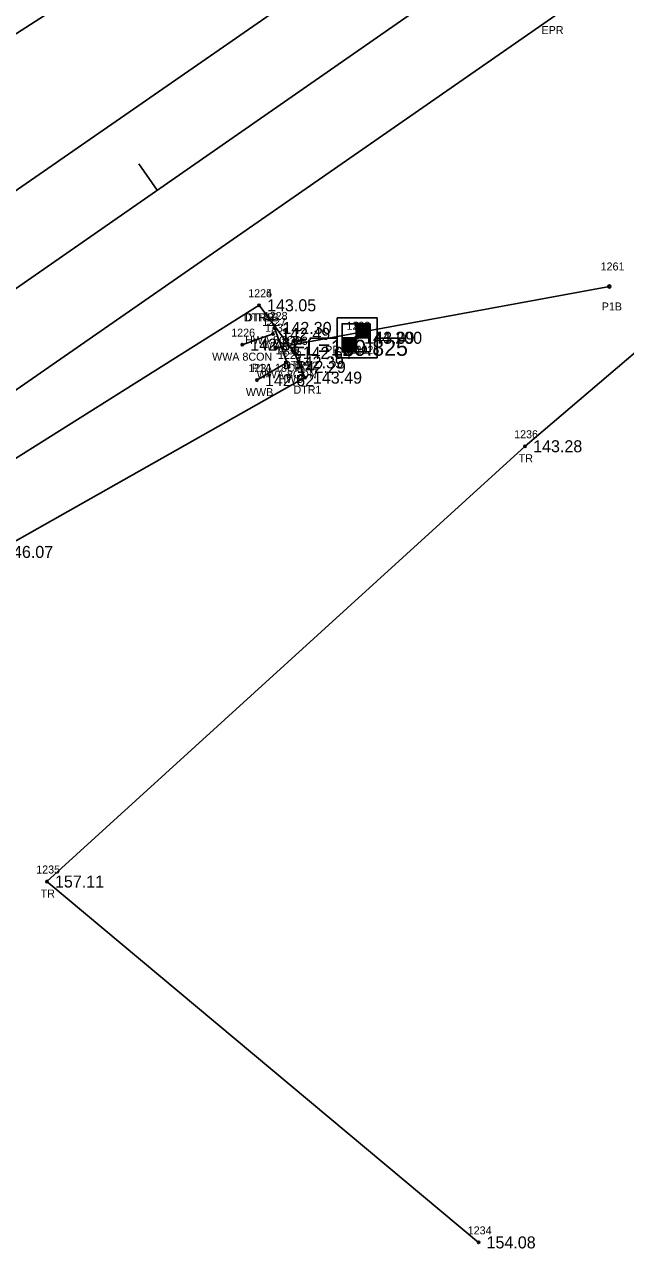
# Model space of a CAD drawing. Extents: x 2449052 to 2452984, y 1012343 to 1015262.
# Drawn here: x 2450757.2 to 2450832.3, y 1013613.6 to 1013766.6 of the extents above; entities that cross this region are included whole.
import ezdxf

# ---------------------------------------------------------------- set-up
doc = ezdxf.new("R2010")
doc.units = 0
for name, color, linetype in [('RD_EX_Bridge', 7, 'Continuous'), ('RD_EX_Bridge_txCode', 7, 'Continuous'), ('RD_EX_DR_Pipe', 7, 'Continuous'), ('RD_EX_DR_Pipe_txCode', 7, 'Continuous'), ('RD_EX_H2O', 7, 'Continuous'), ('RD_EX_H2O_txCode', 7, 'Continuous'), ('RD_EX_Road', 7, 'Continuous'), ('RD_EX_Road_txCode', 7, 'Continuous'), ('RD_EX_TX_Bridge_ELEV', 7, 'Continuous'), ('RD_EX_TX_H2O_ELEV', 7, 'Continuous'), ('RD_EX_TX_VEG_ELEV', 7, 'Continuous'), ('RD_EX_UT', 7, 'Continuous'), ('RD_EX_UT_txCode', 7, 'Continuous'), ('RD_EX_VEG', 7, 'Continuous'), ('RD_EX_VEG_txCode', 7, 'Continuous'), ('RD_HC_Cl', 7, 'Continuous'), ('RD_HC_Data_Tic', 7, 'Continuous'), ('RD_HC_Survey', 7, 'Continuous'), ('RD_HC_Survey_ELEV', 7, 'Continuous'), ('RD_HC_Survey_txCode', 7, 'Continuous'), ('RD_SMD_Locator', 7, 'Continuous'), ('RD_TX_Pipe_ElevEX', 7, 'Continuous')]:
    doc.layers.add(name, color=color, linetype=linetype)

msp = doc.modelspace()

# ---------------------------------------------------------------- linework, layer by layer
at = {"layer": 'RD_EX_Bridge'}
for p, q in [((2450784.38, 1013726.59), (2450788.24, 1013727.94)), ((2450788.41, 1013728.68), (2450790.18, 1013723.81)), ((2450789.94, 1013724.38), (2450786.22, 1013722.16))]:
    msp.add_line(p, q, dxfattribs=at)
at = {"layer": 'RD_EX_DR_Pipe'}
msp.add_line((2450788.58, 1013726.2), (2450830.24, 1013733.86), dxfattribs=at)
at = {"layer": 'RD_EX_H2O'}
for points in [[(2450167.46, 1013291.72), (2450167.1, 1013295.75), (2450175.19, 1013302.21), (2450253.51, 1013357.72), (2450334.87, 1013415.7), (2450415.19, 1013473.64), (2450493.27, 1013528.65), (2450573.99, 1013585.66), (2450651, 1013636.62), (2450748.48, 1013707.64), (2450786.48, 1013731.51)], [(2450167.46, 1013291.72), (2450171.71, 1013290.19), (2450180.8, 1013296.66), (2450259.89, 1013349.14), (2450344.33, 1013402.02), (2450412.23, 1013445.13), (2450424.15, 1013461.12), (2450474.5, 1013497.19), (2450500.92, 1013517.59), (2450581.65, 1013574.66), (2450655.67, 1013631.45), (2450753.63, 1013700.7), (2450792.21, 1013722.47), (2450790.93, 1013725.57), (2450786.48, 1013731.51)]]:
    msp.add_lwpolyline(points, dxfattribs=at)
at = {"layer": 'RD_EX_Road'}
for points in [[(2449674.89, 1012994.69), (2449752.35, 1013048.28), (2449834.92, 1013105.96), (2449914.72, 1013161.11), (2449995.66, 1013217.59), (2450075.29, 1013272.9), (2450081.34, 1013277.24), (2450093.41, 1013285.64), (2450155.49, 1013328.69), (2450236.05, 1013384.7), (2450317.88, 1013441.24), (2450398.87, 1013497.28), (2450477.09, 1013551.76), (2450555.6, 1013606.73), (2450600.18, 1013637.7), (2450618.08, 1013649.65), (2450627.95, 1013656.57), (2450636.43, 1013662.28), (2450733.79, 1013730.39), (2450811.43, 1013784.18), (2450891.39, 1013839.9), (2450907.04, 1013850.14)], [(2449685.94, 1012977.62), (2449764.81, 1013032.3), (2449846, 1013088.39), (2449925.85, 1013144.07), (2450006.8, 1013200.56), (2450086.45, 1013256.14), (2450125.67, 1013283.43), (2450163.55, 1013309.93), (2450166.36, 1013312.09), (2450247.44, 1013367.98), (2450329.19, 1013424.41), (2450410.32, 1013481.09), (2450488.38, 1013535.38), (2450567.5, 1013590.14), (2450648.09, 1013646.13), (2450745.08, 1013713.3), (2450823, 1013767.39), (2450902.19, 1013823.2), (2450918.14, 1013833.95)]]:
    msp.add_lwpolyline(points, dxfattribs=at)
at = {"layer": 'RD_EX_UT'}
for p, q in [((2450801.24, 1013729.96), (2450796.24, 1013729.96)), ((2450796.24, 1013729.96), (2450796.24, 1013724.96)), ((2450801.24, 1013724.96), (2450801.24, 1013729.96)), ((2450792.81, 1013727.4), (2450796.28, 1013727.4)), ((2450801.17, 1013727.4), (2450804.81, 1013727.4)), ((2450796.24, 1013724.96), (2450801.24, 1013724.96))]:
    msp.add_line(p, q, dxfattribs=at)
at = {"layer": 'RD_EX_VEG'}
for points in [[(2450511.25, 1013744.81), (2450612.22, 1013672.34), (2450883.9, 1013848.07), (2451091.43, 1014003.45), (2451271.45, 1014121.26), (2451583.45, 1014347.48), (2451819.08, 1014511.44), (2452219.54, 1014796.6), (2452332.78, 1014867.52)], [(2450813.9, 1013614.45), (2450759.99, 1013659.53), (2450819.72, 1013713.9), (2450939.16, 1013815.82), (2451225.29, 1014005.48), (2451628.56, 1014273.87), (2452372.22, 1014794.45)]]:
    msp.add_lwpolyline(points, dxfattribs=at)
at = {"layer": 'RD_HC_Cl'}
msp.add_line((2449680.91, 1012986.23), (2452350.19, 1014841.68), dxfattribs=at)
at = {"layer": 'RD_HC_Data_Tic'}
msp.add_line((2450773.75, 1013745.87), (2450771.47, 1013749.16), dxfattribs=at)
at = {"layer": 'RD_HC_Survey'}
for p, q in [((2450798.6, 1013729.2), (2450798.6, 1013725.7)), ((2450798.62, 1013729.2), (2450798.62, 1013727.45)), ((2450798.64, 1013729.2), (2450798.64, 1013727.45)), ((2450798.66, 1013729.2), (2450798.66, 1013727.45)), ((2450798.69, 1013729.2), (2450798.69, 1013727.45)), ((2450798.71, 1013729.2), (2450798.71, 1013727.45)), ((2450798.74, 1013729.2), (2450798.74, 1013727.45)), ((2450798.76, 1013729.2), (2450798.76, 1013727.45)), ((2450798.79, 1013729.2), (2450798.79, 1013727.45)), ((2450798.81, 1013729.2), (2450798.81, 1013727.45)), ((2450798.84, 1013729.2), (2450798.84, 1013727.45)), ((2450798.86, 1013729.2), (2450798.86, 1013727.45)), ((2450798.89, 1013729.2), (2450798.89, 1013727.45)), ((2450798.91, 1013729.2), (2450798.91, 1013727.45)), ((2450798.94, 1013729.2), (2450798.94, 1013727.45)), ((2450798.96, 1013729.2), (2450798.96, 1013727.45)), ((2450798.99, 1013729.2), (2450798.99, 1013727.45)), ((2450799.01, 1013729.2), (2450799.01, 1013727.45)), ((2450799.04, 1013729.2), (2450799.04, 1013727.45)), ((2450799.06, 1013729.2), (2450799.06, 1013727.45)), ((2450799.09, 1013729.2), (2450799.09, 1013727.45)), ((2450799.11, 1013729.2), (2450799.11, 1013727.45)), ((2450799.14, 1013729.2), (2450799.14, 1013727.45)), ((2450799.16, 1013729.2), (2450799.16, 1013727.45)), ((2450799.18, 1013729.2), (2450799.18, 1013727.45)), ((2450799.21, 1013729.2), (2450799.21, 1013727.45)), ((2450799.23, 1013729.2), (2450799.23, 1013727.45)), ((2450799.26, 1013729.2), (2450799.26, 1013727.45)), ((2450799.28, 1013729.2), (2450799.28, 1013727.45)), ((2450799.31, 1013729.2), (2450799.31, 1013727.45)), ((2450799.33, 1013729.2), (2450799.33, 1013727.45)), ((2450799.36, 1013729.2), (2450799.36, 1013727.45)), ((2450799.38, 1013729.2), (2450799.38, 1013727.45)), ((2450799.41, 1013729.2), (2450799.41, 1013727.45)), ((2450799.43, 1013729.2), (2450799.43, 1013727.45)), ((2450799.46, 1013729.2), (2450799.46, 1013727.45)), ((2450799.48, 1013729.2), (2450799.48, 1013727.45)), ((2450799.51, 1013729.2), (2450799.51, 1013727.45)), ((2450799.53, 1013729.2), (2450799.53, 1013727.45)), ((2450799.56, 1013729.2), (2450799.56, 1013727.45)), ((2450799.58, 1013729.2), (2450799.58, 1013727.45)), ((2450799.61, 1013729.2), (2450799.61, 1013727.45)), ((2450799.63, 1013729.2), (2450799.63, 1013727.45)), ((2450799.65, 1013729.2), (2450799.65, 1013727.45)), ((2450799.68, 1013729.2), (2450799.68, 1013727.45)), ((2450799.7, 1013729.2), (2450799.7, 1013727.45)), ((2450799.73, 1013729.2), (2450799.73, 1013727.45)), ((2450799.75, 1013729.2), (2450799.75, 1013727.45)), ((2450799.78, 1013729.2), (2450799.78, 1013727.45)), ((2450799.8, 1013729.2), (2450799.8, 1013727.45)), ((2450799.83, 1013729.2), (2450799.83, 1013727.45)), ((2450799.85, 1013729.2), (2450799.85, 1013727.45)), ((2450799.88, 1013729.2), (2450799.88, 1013727.45)), ((2450799.9, 1013729.2), (2450799.9, 1013727.45)), ((2450799.93, 1013729.2), (2450799.93, 1013727.45)), ((2450799.95, 1013729.2), (2450799.95, 1013727.45)), ((2450799.98, 1013729.2), (2450799.98, 1013727.45)), ((2450800, 1013729.2), (2450800, 1013727.45)), ((2450800.03, 1013729.2), (2450800.03, 1013727.45)), ((2450800.05, 1013729.2), (2450800.05, 1013727.45)), ((2450800.08, 1013729.2), (2450800.08, 1013727.45)), ((2450800.1, 1013729.2), (2450800.1, 1013727.45)), ((2450800.13, 1013729.2), (2450800.13, 1013727.45)), ((2450800.15, 1013729.2), (2450800.15, 1013727.45)), ((2450800.17, 1013729.2), (2450800.17, 1013727.45)), ((2450800.2, 1013729.2), (2450800.2, 1013727.45)), ((2450800.22, 1013729.2), (2450800.22, 1013727.45)), ((2450800.25, 1013729.2), (2450800.25, 1013727.45)), ((2450800.27, 1013729.2), (2450800.27, 1013727.45)), ((2450800.3, 1013729.2), (2450800.3, 1013727.45)), ((2450800.32, 1013729.2), (2450800.32, 1013727.45)), ((2450800.35, 1013727.45), (2450796.85, 1013727.45)), ((2450796.85, 1013727.45), (2450796.85, 1013725.7)), ((2450796.87, 1013727.45), (2450796.87, 1013725.7)), ((2450796.9, 1013727.45), (2450796.9, 1013725.7)), ((2450796.92, 1013727.45), (2450796.92, 1013725.7)), ((2450796.95, 1013727.45), (2450796.95, 1013725.7)), ((2450796.97, 1013727.45), (2450796.97, 1013725.7)), ((2450797, 1013727.45), (2450797, 1013725.7)), ((2450797.02, 1013727.45), (2450797.02, 1013725.7)), ((2450797.05, 1013727.45), (2450797.05, 1013725.7)), ((2450797.07, 1013727.45), (2450797.07, 1013725.7)), ((2450797.1, 1013727.45), (2450797.1, 1013725.7)), ((2450797.12, 1013727.45), (2450797.12, 1013725.7)), ((2450797.14, 1013727.45), (2450797.14, 1013725.7)), ((2450797.17, 1013727.45), (2450797.17, 1013725.7)), ((2450797.19, 1013727.45), (2450797.19, 1013725.7)), ((2450797.22, 1013727.45), (2450797.22, 1013725.7)), ((2450797.24, 1013727.45), (2450797.24, 1013725.7)), ((2450797.27, 1013727.45), (2450797.27, 1013725.7)), ((2450797.29, 1013727.45), (2450797.29, 1013725.7)), ((2450797.32, 1013727.45), (2450797.32, 1013725.7)), ((2450797.34, 1013727.45), (2450797.34, 1013725.7)), ((2450797.37, 1013727.45), (2450797.37, 1013725.7)), ((2450797.39, 1013727.45), (2450797.39, 1013725.7)), ((2450797.42, 1013727.45), (2450797.42, 1013725.7)), ((2450797.44, 1013727.45), (2450797.44, 1013725.7)), ((2450797.47, 1013727.45), (2450797.47, 1013725.7)), ((2450797.49, 1013727.45), (2450797.49, 1013725.7)), ((2450797.52, 1013727.45), (2450797.52, 1013725.7)), ((2450797.54, 1013727.45), (2450797.54, 1013725.7)), ((2450797.57, 1013727.45), (2450797.57, 1013725.7)), ((2450797.59, 1013727.45), (2450797.59, 1013725.7)), ((2450797.62, 1013727.45), (2450797.62, 1013725.7)), ((2450797.64, 1013727.45), (2450797.64, 1013725.7)), ((2450797.66, 1013727.45), (2450797.66, 1013725.7)), ((2450797.69, 1013727.45), (2450797.69, 1013725.7)), ((2450797.71, 1013727.45), (2450797.71, 1013725.7)), ((2450797.74, 1013727.45), (2450797.74, 1013725.7)), ((2450797.76, 1013727.45), (2450797.76, 1013725.7)), ((2450797.79, 1013727.45), (2450797.79, 1013725.7)), ((2450797.81, 1013727.45), (2450797.81, 1013725.7)), ((2450797.84, 1013727.45), (2450797.84, 1013725.7)), ((2450797.86, 1013727.45), (2450797.86, 1013725.7)), ((2450797.89, 1013727.45), (2450797.89, 1013725.7)), ((2450797.91, 1013727.45), (2450797.91, 1013725.7)), ((2450797.94, 1013727.45), (2450797.94, 1013725.7)), ((2450797.96, 1013727.45), (2450797.96, 1013725.7)), ((2450797.99, 1013727.45), (2450797.99, 1013725.7)), ((2450798.01, 1013727.45), (2450798.01, 1013725.7)), ((2450798.04, 1013727.45), (2450798.04, 1013725.7)), ((2450798.06, 1013727.45), (2450798.06, 1013725.7)), ((2450798.09, 1013727.45), (2450798.09, 1013725.7)), ((2450798.11, 1013727.45), (2450798.11, 1013725.7)), ((2450798.13, 1013727.45), (2450798.13, 1013725.7)), ((2450798.16, 1013727.45), (2450798.16, 1013725.7)), ((2450798.18, 1013727.45), (2450798.18, 1013725.7)), ((2450798.21, 1013727.45), (2450798.21, 1013725.7)), ((2450798.23, 1013727.45), (2450798.23, 1013725.7)), ((2450798.26, 1013727.45), (2450798.26, 1013725.7)), ((2450798.28, 1013727.45), (2450798.28, 1013725.7)), ((2450798.31, 1013727.45), (2450798.31, 1013725.7)), ((2450798.33, 1013727.45), (2450798.33, 1013725.7)), ((2450798.36, 1013727.45), (2450798.36, 1013725.7)), ((2450798.38, 1013727.45), (2450798.38, 1013725.7)), ((2450798.41, 1013727.45), (2450798.41, 1013725.7)), ((2450798.43, 1013727.45), (2450798.43, 1013725.7)), ((2450798.46, 1013727.45), (2450798.46, 1013725.7)), ((2450798.48, 1013727.45), (2450798.48, 1013725.7)), ((2450798.51, 1013727.45), (2450798.51, 1013725.7)), ((2450798.53, 1013727.45), (2450798.53, 1013725.7)), ((2450798.56, 1013727.45), (2450798.56, 1013725.7)), ((2450798.58, 1013727.45), (2450798.58, 1013725.7))]:
    msp.add_line(p, q, dxfattribs=at)
msp.add_lwpolyline([(2450800.35, 1013729.2), (2450796.85, 1013729.2), (2450796.85, 1013725.7), (2450800.35, 1013725.7)], close=True, dxfattribs=at)
at = {"layer": 'RD_SMD_Locator'}
for centre, radius in [((2450830.24, 1013733.86), 0.2), ((2450786.48, 1013731.51), 0.15), ((2450786.48, 1013731.51), 0.15), ((2450788.24, 1013727.94), 0.15), ((2450788.41, 1013728.68), 0.15), ((2450784.38, 1013726.59), 0.15), ((2450788.58, 1013726.2), 0.2), ((2450798.6, 1013727.45), 0.15), ((2450798.75, 1013727.45), 0.15), ((2450790.93, 1013725.57), 0.15), ((2450789.94, 1013724.38), 0.15), ((2450790.18, 1013723.81), 0.15), ((2450786.22, 1013722.16), 0.15), ((2450792.21, 1013722.47), 0.15), ((2450819.72, 1013713.9), 0.15), ((2450759.99, 1013659.53), 0.15), ((2450813.9, 1013614.45), 0.15)]:
    msp.add_circle(centre, radius, dxfattribs=at)

# ---------------------------------------------------------------- texts
at = {"layer": 'RD_EX_Bridge_txCode'}
for s, p in [('1227', (2450786.89, 1013728.94)), ('1228', (2450787.07, 1013729.68)), ('1226', (2450783.01, 1013727.59)), ('HWA 8CON', (2450784.74, 1013726.68)), ('WWB', (2450786.86, 1013725.94)), ('1230', (2450788.56, 1013725.38)), ('WWA 8CON', (2450780.62, 1013724.59)), ('1229', (2450788.84, 1013724.81)), ('1231', (2450785.16, 1013723.16)), ('WWA 8CON', (2450786.18, 1013722.38)), ('HWB', (2450788.89, 1013721.81)), ('WWB', (2450784.84, 1013720.16))]:
    msp.add_text(s, height=1, dxfattribs=at).set_placement(p)
at = {"layer": 'RD_EX_DR_Pipe_txCode'}
for s, p in [('1261', (2450829.15, 1013735.86)), ('P1B', (2450829.29, 1013730.86)), ('1232', (2450787.23, 1013728.2)), ('P1A 18CP', (2450785.57, 1013723.2))]:
    msp.add_text(s, height=1, dxfattribs=at).set_placement(p)
at = {"layer": 'RD_EX_H2O_txCode'}
for s, p in [('1224', (2450785.13, 1013732.51)), ('1225', (2450785.13, 1013732.51)), ('DTR1B', (2450784.57, 1013729.51)), ('DTRB', (2450784.74, 1013729.51)), ('1223', (2450789.58, 1013726.57)), ('DTR1', (2450789.49, 1013723.57)), ('1222', (2450790.87, 1013723.47)), ('DTR1', (2450790.78, 1013720.47))]:
    msp.add_text(s, height=1, dxfattribs=at).set_placement(p)
at = {"layer": 'RD_EX_Road_txCode'}
msp.add_text('EPR', height=1, dxfattribs=at).set_placement((2450821.77, 1013765.39))
at = {"layer": 'RD_EX_TX_Bridge_ELEV'}
for s, p in [('142.30', (2450789.41, 1013727.93)), ('142.49', (2450789.24, 1013727.19)), ('142.62', (2450785.38, 1013725.84)), ('142.39', (2450790.94, 1013723.63)), ('142.29', (2450791.18, 1013723.06)), ('142.62', (2450787.22, 1013721.41))]:
    msp.add_text(s, height=1.5, dxfattribs=at).set_placement(p)
at = {"layer": 'RD_EX_TX_H2O_ELEV'}
for s, p in [('143.05', (2450787.48, 1013730.76)), ('143.05', (2450787.48, 1013730.76)), ('142.64', (2450791.93, 1013724.82)), ('143.49', (2450793.21, 1013721.72)), ('146.07', (2450754.63, 1013699.95))]:
    msp.add_text(s, height=1.5, dxfattribs=at).set_placement(p)
at = {"layer": 'RD_EX_TX_VEG_ELEV'}
for s, p in [('143.28', (2450820.72, 1013713.15)), ('157.11', (2450760.99, 1013658.78)), ('154.08', (2450814.9, 1013613.7))]:
    msp.add_text(s, height=1.5, dxfattribs=at).set_placement(p)
at = {"layer": 'RD_EX_UT_txCode'}
for s, p in [('1233', (2450797.4, 1013728.45)), ('PP B22025', (2450794.74, 1013725.45))]:
    msp.add_text(s, height=1, dxfattribs=at).set_placement(p)
at = {"layer": 'RD_EX_VEG_txCode'}
for s, p in [('1236', (2450818.35, 1013714.9)), ('TR', (2450818.92, 1013711.9)), ('1235', (2450758.65, 1013660.53)), ('TR', (2450759.2, 1013657.53)), ('1234', (2450812.55, 1013615.45))]:
    msp.add_text(s, height=1, dxfattribs=at).set_placement(p)
at = {"layer": 'RD_HC_Survey_ELEV'}
for s, p in [('144.200', (2450799.6, 1013726.7)), ('143.09', (2450799.75, 1013726.7))]:
    msp.add_text(s, height=1.5, dxfattribs=at).set_placement(p)
at = {"layer": 'RD_HC_Survey_txCode'}
for s, p in [('9', (2450798.31, 1013728.45)), ('BM 1', (2450797.05, 1013725.45))]:
    msp.add_text(s, height=1, dxfattribs=at).set_placement(p)
at = {"layer": 'RD_TX_Pipe_ElevEX'}
msp.add_text('EL=139.825', height=2, dxfattribs=at).set_placement((2450790.58, 1013725.2))

doc.saveas('drawing.dxf')
